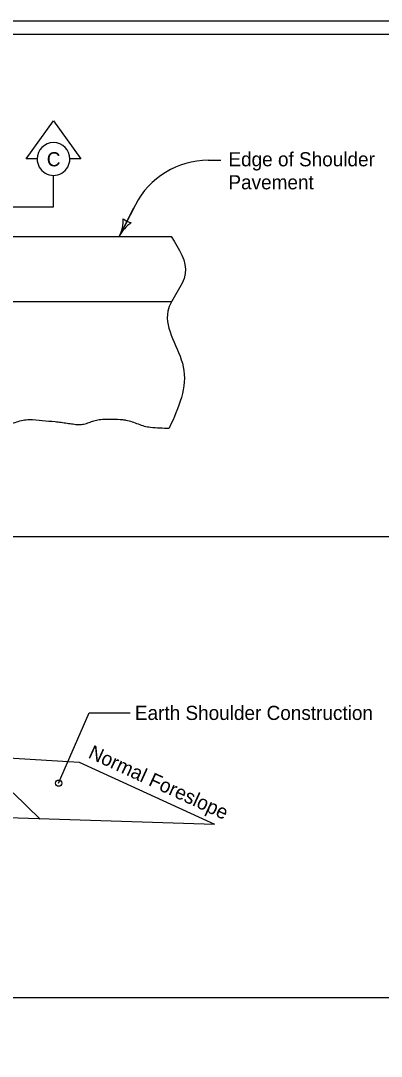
# Model space of a CAD drawing. Extents: x 9538 to 81668, y 7600 to 11751.
# Drawn here: x 29808 to 30215, y 8774 to 9944 of the extents above; entities that cross this region are included whole.
import ezdxf

# ---------------------------------------------------------------- set-up
doc = ezdxf.new("R2010")
doc.units = 0
for name, color, linetype in [('Default', 7, 'Continuous'), ('DsnShtMinorGrid14', 7, 'Continuous'), ('dsnStdNameDate', 7, 'Continuous'), ('dsnStdNote', 7, 'Continuous'), ('dsnStdPattern', 7, 'Continuous'), ('dsnStdShading', 7, 'Continuous'), ('dsnStdTable', 7, 'Continuous')]:
    doc.layers.add(name, color=color, linetype=linetype)

msp = doc.modelspace()

# ---------------------------------------------------------------- linework, layer by layer
at = {"layer": 'Default'}
msp.add_lwpolyline([(28132.6, 9944), (31267.6, 9944), (31267.6, 7924), (28132.6, 7924)], close=True, dxfattribs=at)
at = {"layer": 'DsnShtMinorGrid14'}
msp.add_circle((29850.7, 9082.6), 3.54, dxfattribs=at)
at = {"layer": 'dsnStdNameDate'}
for p, q in [((30303.1, 9361), (28147.6, 9361)), ((30303.1, 8840), (28147.6, 8840))]:
    msp.add_line(p, q, dxfattribs=at)
at = {"layer": 'dsnStdNote'}
for p, q in [((30019.6, 9786.3), (30033.9, 9786.3)), ((29937.3, 9736), (29919.1, 9700.3)), ((29850.7, 9082.6), (29885, 9162)), ((29885, 9162), (29931.4, 9162))]:
    msp.add_line(p, q, dxfattribs=at)
for centre, radius, start, end in [((30019.6, 9693.9), 92.4, 90, 152.9341), ((29881.2, 9719.6), 42.5, 332.9341, 1.0066), ((29956.9, 9681), 42.5, 124.8616, 152.9341), ((29935.3, 9732), 16.4, 225.2008, 260.6675)]:
    msp.add_arc(centre, radius, start, end, dxfattribs=at)
at = {"layer": 'dsnStdPattern'}
for p, q in [((29844.9, 9733.8), (29844.9, 9769.3)), ((29756.8, 9733.8), (29844.9, 9733.8))]:
    msp.add_line(p, q, dxfattribs=at)
msp.add_lwpolyline([(29826.4, 9787.8), (29814.1, 9787.8), (29844.9, 9830.9), (29875.7, 9787.8), (29863.4, 9787.8)], dxfattribs=at)
for start, end in [(0.0008, 179.9992), (179.9992, 0.0008)]:
    msp.add_arc((29844.9, 9787.8), 18.5, start, end, dxfattribs=at)
at = {"layer": 'dsnStdShading'}
msp.add_line((28147.6, 9929), (31243.2, 9929), dxfattribs=at)
at = {"layer": 'dsnStdTable'}
for p, q in [((29935.3, 9732.1), (29919.1, 9700.3)), ((28364, 9700.3), (29977.7, 9700.3)), ((28552, 9626.7), (29978, 9626.7)), ((29739.2, 9114.6), (29874, 9106.2)), ((29874, 9106.2), (30026.6, 9036.2)), ((29799.2, 9071.7), (29829.7, 9042)), ((29543.2, 9052), (30026.6, 9036.2))]:
    msp.add_line(p, q, dxfattribs=at)
for points in [[(29977.7, 9700.3), (29993.6, 9658.3), (29974, 9615.7), (29991.4, 9553.1), (29975.6, 9483.8)], [(29695.9, 9487.6), (29697.9, 9487.7), (29705.5, 9488.2), (29713.1, 9488.8), (29720.6, 9489.6), (29728.1, 9490.5), (29732.9, 9491.5), (29737.6, 9493), (29742.2, 9494.3), (29744.6, 9494.8), (29747, 9495.1), (29753.5, 9495.1), (29760.1, 9494.4), (29766.7, 9493.4), (29773.2, 9492.2), (29777.2, 9491.3), (29781.2, 9490.1), (29785.2, 9489), (29789.2, 9488.3), (29792.7, 9488.2), (29796.3, 9488.7), (29803.4, 9490.7), (29810.5, 9492.7), (29817.7, 9493.4), (29832.2, 9492.4), (29846.7, 9491.1), (29853.5, 9490.3), (29860.2, 9489.3), (29866.9, 9488.4), (29873.6, 9487.7), (29879.3, 9488.3), (29885, 9490.1), (29890.6, 9492.1), (29896.4, 9493.4), (29903.9, 9493.9), (29911.5, 9494), (29922.8, 9493.3), (29926.6, 9492.8), (29933.6, 9491), (29940.5, 9488.4), (29947.4, 9486.1), (29954.5, 9484.8), (29975.6, 9483.8)]]:
    msp.add_spline(points, degree=3, dxfattribs=at)

# ---------------------------------------------------------------- texts
at = {"layer": 'dsnStdNote'}
for s, p in [('Edge of Shoulder', (30042.4, 9779.5)), ('Pavement', (30042.4, 9753.5)), ('Earth Shoulder Construction', (29936.8, 9154))]:
    msp.add_text(s, height=16, dxfattribs=at).set_placement(p)
msp.add_text('Normal Foreslope', height=16, rotation=335.372, dxfattribs=at).set_placement((29883, 9111.8))
at = {"layer": 'dsnStdPattern'}
msp.add_text('C', height=16, dxfattribs=at).set_placement((29837.3, 9779.5))

doc.saveas('drawing.dxf')
